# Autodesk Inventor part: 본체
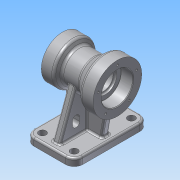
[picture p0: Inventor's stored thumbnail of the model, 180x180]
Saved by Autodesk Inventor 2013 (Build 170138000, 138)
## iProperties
Created: 2015-08
Part Number: 본체
Material: 알루미늄 6061
Document SubType Name: Modeling
Designer: Administrator
Density: 2.71 g/cm^3
Mass: 1062.79 g
Surface Area: 749.652 cm^2
Volume: 392.172 cm^3
Author: Administrator
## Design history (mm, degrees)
sketch "스케치1"
  geometry: L1 (-40, 0)-(50, 0); L2 (-40, 0)-(-40, 35); L3 (-40, 35)-(-20, 35); L4 (-20, 35)-(-14.804, 26); L5 (-14.804, 26)-(13.315, 26); L6 (13.315, 26)-(30, 40); L7 (30, 40)-(50, 40); L8 (50, 40)-(50, 0); 2 further points
  constraints: 16 end point, 3 parallel, 2 perpendicular, 1 horizontal, 1 horizontal alignment, 1 midpoint
  dimensions: "d0" = 90 distance of L1.start L1.end; "d1" = 40 distance of point (0, 0) L1.start; "d2" = 70 diameter of L3 L1; "d3" = 80 diameter of L7 L1; "d5" = 60 deg angle of L5 L4; "d6" = 40 deg angle of L5 L6; "d7" = 20 distance of L2.end L3.end; "d8" = 20 distance of L6.end L7.end; "d9" = 52 diameter of L5 L1
revolve "회전1" sketch "스케치1" stored, may be unused: angle "d10" = 90 deg
node "작업 평면1"
sketch "스케치2"
  geometry: L1 (-40, -61)-(40, -61); L2 (40, -61)-(40, 61); L3 (40, 61)-(-40, 61); L4 (-40, 61)-(-40, -61); L5 (-40, -35)-(-40, 35) reference; 2 further points
  constraints: 8 end point, 2 midpoint, 2 parallel, 1 horizontal, 1 perpendicular
  dimensions: "d12" = 80 distance of L3.end L2.end; "d13" = 122 distance of L2.end L1.end
extrude "돌출1" join sketch "스케치2" distance "d14" = 12; taper "d15" = 0 deg
fillet "모깎기1" dims "d16" = 14
sketch "스케치3"
  geometry: L1 (-61, -78)-(61, -78) reference; L2 (61, -78)-(61, -90) reference; L3 (61, -90)-(-61, -90) reference; L4 (-61, -90)-(-61, -78) reference; L5 (-25.091, -6.815)-(-51, -78); L6 (25.091, -6.815)-(51, -78); A1 r 26 centre (0, 0) between (-25.091, -6.815) and (25.091, -6.815) reference; 1 further point
  constraints: 4 end point, 2 point on circle, 2 point on line
  dimensions: "d17" = 10 distance from line of L5.end L4; "d18" = 10 distance from line of L6.end L2; "d19" = 70 deg angle of L1 L6; "d20" = 70 deg angle of L1 L5
extrude "돌출2" join sketch "스케치3" stored distance "d21" = 12; taper "d22" = 0 deg
sketch "스케치4"
  geometry: L1 (40, 35)-(40, -35) reference; L2 (40, -35)-(20, -35) reference; L3 (20, -35)-(14.804, -26) reference; L4 (14.804, -26)-(6, -26) reference; L5 (6, -26)-(6, -78) reference; L6 (6, -78)-(40, -78) reference; L7 (40, -78)-(40, -90) reference; L8 (40, -90)-(-40, -90) reference; L9 (-40, -90)-(-40, -78) reference; L10 (-40, -78)-(-6, -78) reference; L11 (-6, -78)-(-6, -26) reference; L12 (-6, -26)-(-13.315, -26) reference; L13 (-13.315, -26)-(-30, -40) reference; L14 (-30, -40)-(-50, -40) reference; L15 (-50, -40)-(-50, 40) reference; L16 (-50, 40)-(-30, 40) reference; L17 (-30, 40)-(-13.315, 26) reference; L18 (-13.315, 26)-(14.804, 26) reference; L19 (14.804, 26)-(20, 35) reference; L20 (20, 35)-(40, 35) reference; L21 (30, -35)-(30, -78); L22 (-36.7, -40)-(-30, -78); 1 further point
  constraints: 4 end point, 3 point on line, 1 midpoint, 1 perpendicular
  dimensions: "d23" = 10 distance between parallel lines of L21 L7; "d24" = 10 distance from line of L9 L22.end; "d25" = 80 deg angle of L10 L22
  node "절단 모서리 투영2"
feature "리브1" dims "d26" = 1, "d27" = 12, "d28" = 0, "d29" = 0, "d30" = 1, "d31" = 1
feature "리브2" dims "d32" = 1, "d33" = 12, "d34" = 0, "d35" = 0, "d36" = 1, "d37" = 1
hole "구멍1" diameter "d40" = 12; stored, may be unused: countersink angle "d44" = 90 deg, drill point angle "d46" = 0 deg; dims "d38" = 10, "d39" = 10, "d41" = 6, "d42" = 4, "d43" = 2, "d45" = 8
hole "구멍2" diameter "d55" = 32; stored, may be unused: countersink angle "d59" = 90 deg, drill point angle "d61" = 0 deg; dims "d53" = 10, "d54" = 10, "d56" = 6, "d57" = 40, "d58" = 17, "d60" = 8
hole "구멍3" diameter "d64" = 38; stored, may be unused: countersink angle "d68" = 90 deg, drill point angle "d70" = 0 deg; dims "d62" = 10, "d63" = 10, "d65" = 6, "d66" = 52, "d67" = 20, "d69" = 23
fillet "모깎기2" dims "d71" = 3
fillet "모깎기3" dims "d72" = 5
sketch "스케치5"
  geometry: L1 (0, 0)-(-33, 0); C1 r 40 at (0, 0) reference; 1 further point
  constraints: 2 end point, 1 coincident, 1 horizontal
  dimensions: "d73" = 33 distance of L1.start L1.end
hole "구멍4" sketch "스케치5" at (-33, 0) diameter "d74" = 3.242; stored, may be unused: countersink angle "d78" = 90 deg, drill point angle "d80" = 118 deg; dims "d75" = 10, "d76" = 52, "d77" = 20, "d79" = 13
sketch "스케치6"
  geometry: L1 (0, 0)-(27, 0); C1 r 35 at (0, 0) reference; 1 further point
  constraints: 2 end point, 1 coincident, 1 horizontal
  dimensions: "d84" = 27 distance of L1.start L1.end
hole "구멍5" sketch "스케치6" at (27, 0) diameter "d85" = 3.242; stored, may be unused: countersink angle "d89" = 90 deg, drill point angle "d91" = 118 deg; dims "d86" = 10, "d87" = 52, "d88" = 20, "d90" = 13
sketch "스케치7"
  geometry: L1 (78, -6)-(78, -51) reference; L2 (54, -30)-(60, -30); L3 (60, -18)-(54, -18); A1 r 26 centre (0, 0) between (6.815, -25.091) and (25.298, -6) reference; A2 r 6 centre (60, -24) between (60, -30) and (60, -18); A3 r 6 centre (54, -24) between (54, -18) and (54, -30)
  constraints: 4 end point, 4 point on circle, 4 tangent, 2 centre point, 1 parallel, 1 perpendicular
  dimensions: "d95" = 18 distance from line of L1 A2.centre; "d96" = 18 dimension on A3 A2; "d97" = 12 distance between parallel lines of L3 L2; "d98" = 24 vertical distance of A1.centre A2.centre
extrude "돌출3" cut sketch "스케치7" stored distance "d99" = 12; taper "d100" = 0 deg
sketch "스케치8"
  geometry: L1 (0, 0)-(0, 43.518) reference; L2 (24, 0)-(0, 0) reference; 2 further points
  constraints: 1 other
  dimensions: "d101" = 16 distance from line of point (16, 24) L1; "d102" = 24 distance from line of point (16, 24) L2
feature "엠보싱1" sketch "스케치8" dims "d0" = 90, "d1" = 40, "d2" = 70, "d3" = 80, "d5" = 60 deg, "d6" = 40 deg, "d7" = 20, "d8" = 20, "d9" = 52, "d103" = 0.5, "d104" = 0
fillet "모깎기4" dims "d105" = 3
fillet "모깎기5" dims "d106" = 3
fillet "모깎기6" dims "d107" = 3
fillet "모깎기7" dims "d108" = 3
fillet "모깎기8" dims "d109" = 3
fillet "모깎기9" dims "d110" = 0.3
chamfer "모따기1" distance "d111" = 1; stored, may be unused: second distance "d112" = 2, angle "d113" = 45 deg
sketch "스케치9"
  geometry: L1 (40, 28.621)-(40, 25.379) reference; L2 (-50, 40)-(-50, -40) reference; L3 (33, -78)-(37, -78) reference; L4 (40, -81)-(40, -90) reference; L5 (40, -90)-(-40, -90) reference; L6 (-40, -90)-(-40, -81) reference; L7 (-37, -78)-(-33.575, -78) reference; L8 (-30.621, -74.479)-(-36.263, -42.479) reference; L9 (-39.218, -40)-(-50, -40) reference; L10 (-50, -40)-(-50, -27) reference; L11 (-50, -27)-(-49, -26) reference; L12 (-49, -26)-(-30.3, -26) reference; L13 (-30, -25.7)-(-30, -19) reference; L14 (-27, -16)-(23, -16) reference; L15 (23, -16)-(23, -19.7) reference; L16 (23.3, -20)-(39, -20) reference; L17 (39, -20)-(40, -21) reference; L18 (40, -21)-(40, -35) reference; L19 (40, -35)-(33, -35) reference; L20 (30, -38)-(30, -75) reference; L21 (22.887, 35)-(40, 35) reference; L22 (40, 35)-(40, 28.621) reference; L23 (40, 28.621)-(27, 28.621) reference; L24 (27, 28.621)-(26.026, 27) reference; L25 (26.026, 27)-(27, 25.379) reference; L26 (27, 25.379)-(40, 25.379) reference; L27 (40, 25.379)-(40, 21) reference; L28 (40, 21)-(39, 20) reference; L29 (39, 20)-(23.3, 20) reference; L30 (23, 19.7)-(23, 16) reference; L31 (23, 16)-(-27, 16) reference; L32 (-30, 19)-(-30, 25.7) reference; L33 (-30.3, 26)-(-49, 26) reference; L34 (-49, 26)-(-50, 27) reference; L35 (-50, 27)-(-50, 31.379) reference; L36 (-50, 31.379)-(-37, 31.379) reference; L37 (-37, 31.379)-(-36.026, 33) reference; L38 (-36.026, 33)-(-37, 34.621) reference; L39 (-37, 34.621)-(-50, 34.621) reference; L40 (-50, 34.621)-(-50, 40) reference; L41 (-50, 40)-(-31.82, 40) reference; L42 (-28.606, 38.83)-(-14.71, 27.17) reference; L43 (-11.496, 26)-(11.917, 26) reference; L44 (16.247, 28.5)-(18.557, 32.5) reference; A1 r 3 centre (33, -75) between (30, -75) and (33, -78) reference; A2 r 3 centre (37, -81) between (40, -81) and (37, -78) reference; A3 r 3 centre (-37, -81) between (-37, -78) and (-40, -81) reference; A4 r 3 centre (-33.575, -75) between (-33.575, -78) and (-30.621, -74.479) reference; A5 r 0.3 centre (-30.3, -25.7) between (-30.3, -26) and (-30, -25.7) reference; A6 r 3 centre (-30, -16) between (-30, -19) and (-27, -16) reference; A7 r 0.3 centre (23.3, -19.7) between (23, -19.7) and (23.3, -20) reference; A8 r 3 centre (33, -38) between (33, -35) and (30, -38) reference; A9 r 5 centre (22.887, 30) between (22.887, 35) and (18.557, 32.5) reference; A10 r 0.3 centre (23.3, 19.7) between (23.3, 20) and (23, 19.7) reference; A11 r 3 centre (-30, 16) between (-27, 16) and (-30, 19) reference; A12 r 0.3 centre (-30.3, 25.7) between (-30, 25.7) and (-30.3, 26) reference; A13 r 5 centre (-31.82, 35) between (-28.606, 38.83) and (-31.82, 40) reference; A14 r 5 centre (-11.496, 31) between (-14.71, 27.17) and (-11.496, 26) reference; A15 r 5 centre (11.917, 31) between (11.917, 26) and (16.247, 28.5) reference; 1 further point
  constraints: 1 other
  dimensions: "d114" = 90 distance between parallel lines of L1 L2 (derived); "d115" = 40 deg angle of L43 L42 (derived); "d116" = 60 deg angle of L43 L44 (derived); "d117" = 52 diameter of point (0, 0) L43 (derived)
  node "절단 모서리 투영3"
sketch "스케치10"
  geometry: L1 (-50.282, -76.026)-(-25.407, -7.683) reference; L2 (25.407, -7.683)-(50.282, -76.026) reference; L3 (53.101, -78)-(58, -78) reference; L4 (61, -81)-(61, -90) reference; L5 (61, -90)-(-61, -90) reference; L6 (-61, -90)-(-61, -81) reference; L7 (-58, -78)-(-53.101, -78) reference; L8 (18, -54)-(18, -60) reference; L9 (30, -60)-(30, -54) reference; L10 (-30, -54)-(-30, -60) reference; L11 (-18, -60)-(-18, -54) reference; C1 r 16 at (0, 0) reference; A1 r 3 centre (-53.101, -75) between (-53.101, -78) and (-50.282, -76.026) reference; A2 r 3 centre (-28.226, -6.657) between (-25.407, -7.683) and (-25.306, -5.968) reference; A3 r 26 centre (0, 0) between (25.306, -5.968) and (-25.306, -5.968) reference; A4 r 3 centre (28.226, -6.657) between (25.306, -5.968) and (25.407, -7.683) reference; A5 r 3 centre (53.101, -75) between (50.282, -76.026) and (53.101, -78) reference; A6 r 3 centre (58, -81) between (61, -81) and (58, -78) reference; A7 r 3 centre (-58, -81) between (-58, -78) and (-61, -81) reference; A8 r 6 centre (24, -54) between (30, -54) and (18, -54) reference; A9 r 6 centre (24, -60) between (18, -60) and (30, -60) reference; A10 r 6 centre (-24, -54) between (-18, -54) and (-30, -54) reference; A11 r 6 centre (-24, -60) between (-30, -60) and (-18, -60) reference; 1 further point
  dimensions: "d118" = 48 distance of A9.centre A11.centre (derived)
  node "절단 모서리 투영4"
node "솔리드1"
pattern_linear "직사각형 패턴1" dims "d49" = 94, "d52" = 52
pattern_circular "원형 패턴1" dims angle "d82" = 360 deg
pattern_circular "원형 패턴2" dims angle "d93" = 360 deg
mirror "대칭1"
node "절단 모서리 투영1"
